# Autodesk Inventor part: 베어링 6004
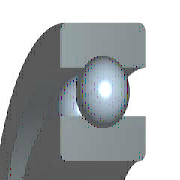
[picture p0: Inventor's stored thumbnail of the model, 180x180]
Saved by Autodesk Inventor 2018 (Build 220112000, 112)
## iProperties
Created: 2012-02
Part Number: 베어링 6004
Material: 강철, 연강
Description: 깊은 그루브 볼 베어링
Document SubType Name: Modeling
Standard: KS B 2023
Designer: mduedu
Standards Organization: KS
Language: ko-KR
Size Designation: 6004 - 20 x 42 x 12
Categories: <MemberInstance><Categories><Category DisplayName="샤프트 부품" InternalName="7f7aeb1f-a693-4053-b835-cee3144e0d98" Mnemonic="SHFT"><Category DisplayName="베어링" Inter
Density: 1 g/cm^3
Appearance: 노란색
IsCustomPart: 1
Author: mduedu
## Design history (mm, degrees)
sketch "스케치" dims "d0" = 5.72 (= -0.26 x WD + 0.26 x BD)
  geometry: L1 (3.14, 15.5)-(8.86, 15.5); L2 (6, 15.5)-(6, 12.64); L3 (6, 15.5)-(6, 18.36); L4 (3.875, 13.586)-(0, 13.586); L5 (0, 10)-(12, 10); L6 (3.875, 17.414)-(0, 17.414); L7 (0, 21)-(12, 21); L8 (12, 10)-(12, 13.586); L9 (8.125, 13.586)-(12, 13.586); L10 (8.125, 17.414)-(12, 17.414); L11 (12, 21)-(12, 17.414); L12 (-1.4, 0)-(8.4, 0) reference; L13 (0, -0.3)-(0, 5.3) reference
  constraints: 22 end point, 4 point on line, 2 collinear, 2 perpendicular, 2 symmetric about line, 1 midpoint, 1 parallel, 14 other
  dimensions: "d9" = 20 diameter of L5 L12 (= WD); "d11" = 42 diameter of L7 L12 (= BD); "d12" = 12 distance between parallel lines of L8 L13 (= KB); "d13" = 27.172 diameter of L9 L12 (= 0.326 x BD + 0.674 x WD)
revolve "본체" stored, may be unused: angle "d6" = 90 deg
revolve "볼" stored, may be unused: angle "d7" = 90 deg
pattern_circular "IDS_ARRAYBALL[SIMPL:T]" dims angle "d3" = 360 deg
body "Solid1"
fillet "모깎기1" dims "d1" = 0.6 (= KRS)
other parameters: "WD" = 20 [user parameter; used in 5 equation terms], "BD" = 42 [user parameter; used in 5 equation terms], "KB" = 12 [user parameter; used in 1 equation term], "KRS" = 0.6 [user parameter; used in 1 equation term], "d4" = 0, "d5" = 0, "d8" = 0, "d14" = 0, "d15" = 0, "BBA" = 0 [user parameter], "BC0" = 5000000 [user parameter], "BC" = 9360000 [user parameter], "BR" = 21 (= 0.5 x BD) [user parameter]
